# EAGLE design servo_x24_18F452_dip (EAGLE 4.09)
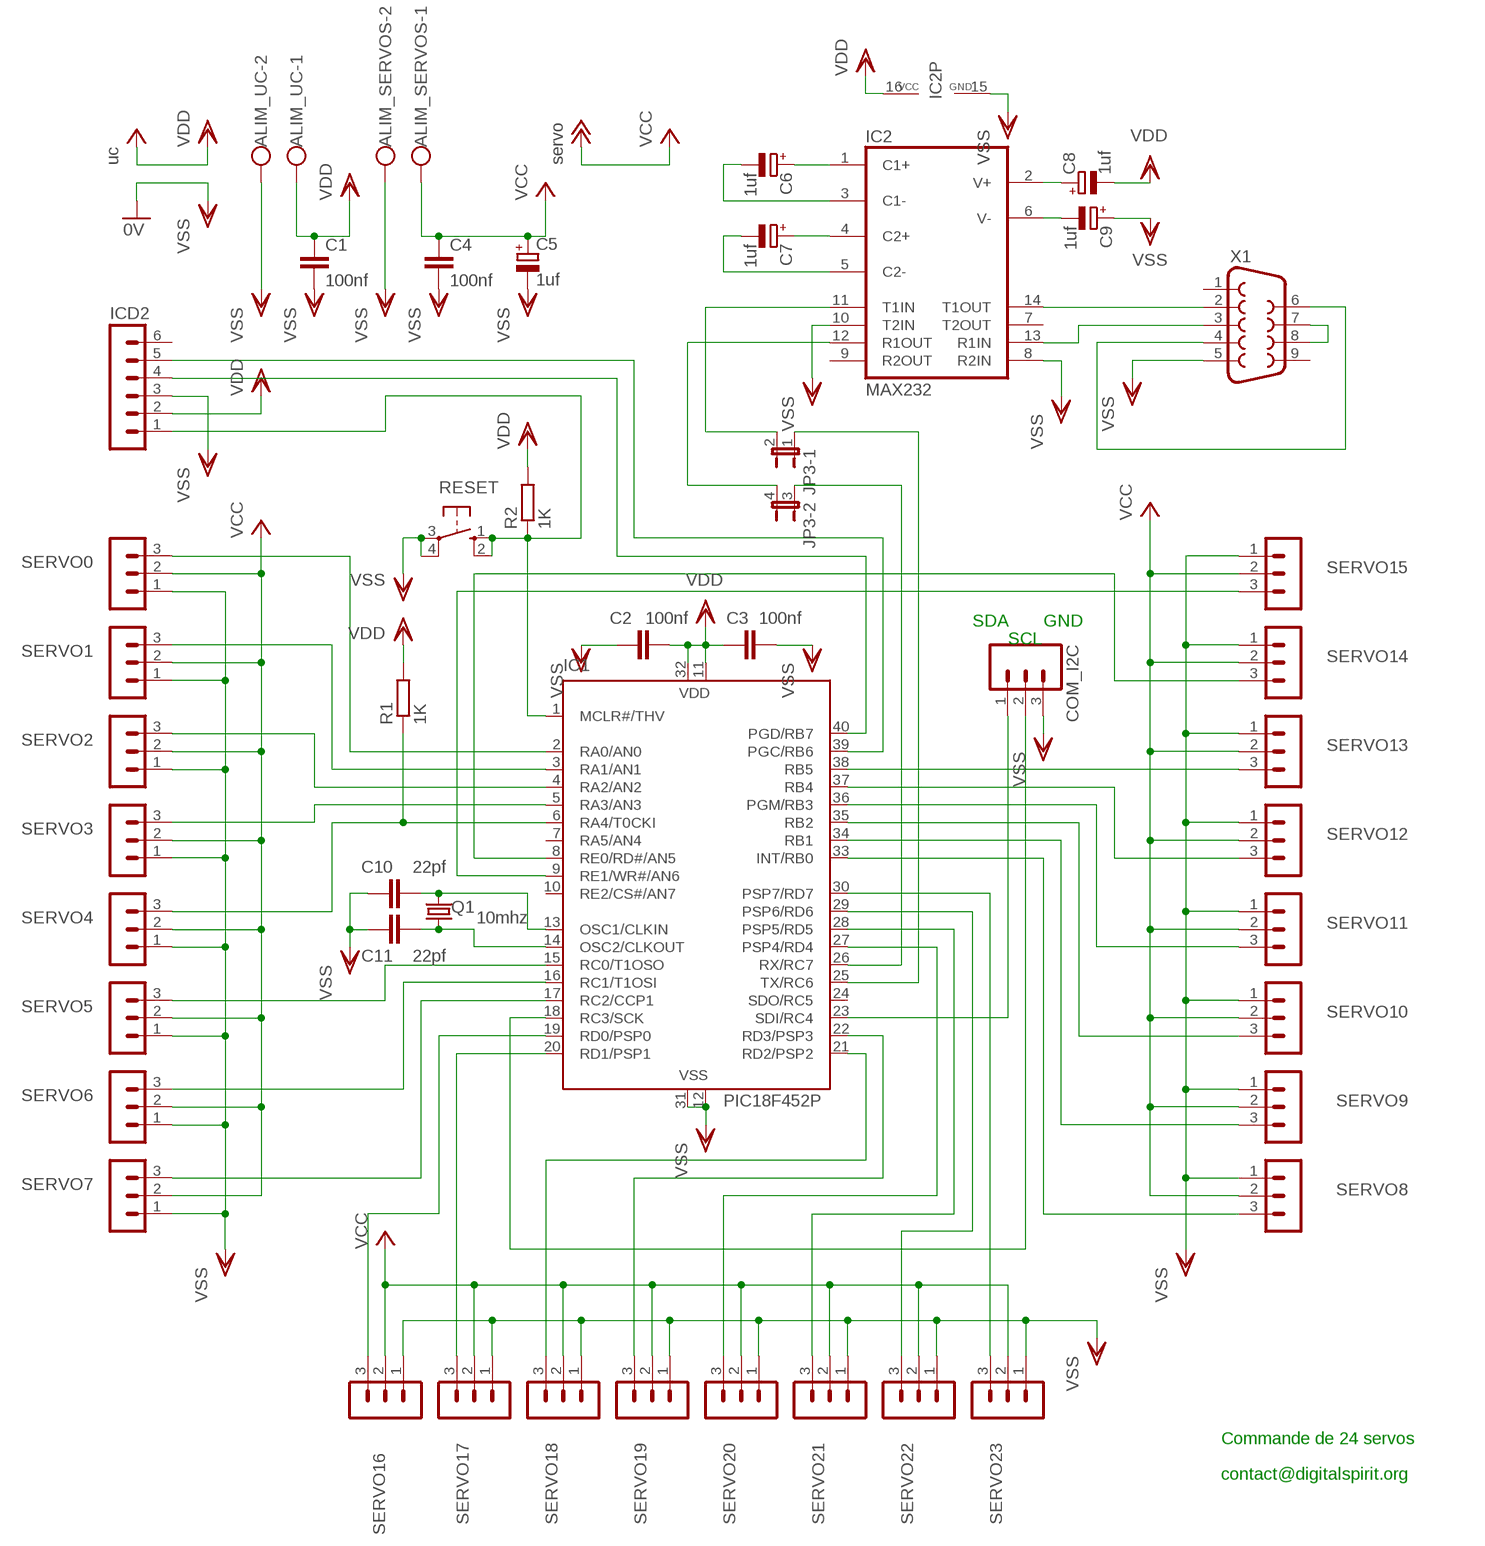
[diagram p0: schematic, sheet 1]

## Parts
ALIM_SERVOS  AK500/2  [AK500/2]
ALIM_UC  AK500/2  [AK500/2]
C1  100nf  C-EU050-025X075  [C050-025X075]
C2  100nf  C-EU050-025X075  [C050-025X075]
C3  100nf  C-EU050-025X075  [C050-025X075]
C4  100nf  C-EU050-025X075  [C050-025X075]
C5  1uf  CPOL-EUE2-4  [E2-4]
C6  1uf  CPOL-EUE2-4  [E2-4]
C7  1uf  CPOL-EUE2-4  [E2-4]
C8  1uf  CPOL-EUE2-4  [E2-4]
C9  1uf  CPOL-EUE2-4  [E2-4]
C10  22pf  C-EU050-024X044  [C050-024X044]
C11  22pf  C-EU050-024X044  [C050-024X044]
COM_I2C  M03  [03P]
IC1  PIC18F452P  PIC16F877P  [DIL40]
IC2  MAX232  [DIL16]
ICD2  MA06-1  [MA06-1]
JP3  JP2QE  [JP2Q]
Q1  10mhz  CRYTALHC49S  [HC49/S]
R1  1K  R-EU_0204/7  [0204/7]
R2  1K  R-EU_0204/7  [0204/7]
RESET  10-XX  [B3F-10XX]
SERVO0  MA03-1  [MA03-1]
SERVO1  MA03-1  [MA03-1]
SERVO2  MA03-1  [MA03-1]
SERVO3  MA03-1  [MA03-1]
SERVO4  MA03-1  [MA03-1]
SERVO5  MA03-1  [MA03-1]
SERVO6  MA03-1  [MA03-1]
SERVO7  MA03-1  [MA03-1]
SERVO8  MA03-1  [MA03-1]
SERVO9  MA03-1  [MA03-1]
SERVO10  MA03-1  [MA03-1]
SERVO11  MA03-1  [MA03-1]
SERVO12  MA03-1  [MA03-1]
SERVO13  MA03-1  [MA03-1]
SERVO14  MA03-1  [MA03-1]
SERVO15  MA03-1  [MA03-1]
SERVO16  MA03-1  [MA03-1]
SERVO17  MA03-1  [MA03-1]
SERVO18  MA03-1  [MA03-1]
SERVO19  MA03-1  [MA03-1]
SERVO20  MA03-1  [MA03-1]
SERVO21  MA03-1  [MA03-1]
SERVO22  MA03-1  [MA03-1]
SERVO23  MA03-1  [MA03-1]
X1  F09H  [F09H]

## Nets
N$1: IC1.2(RA0/AN0) SERVO0.3
N$2: IC1.3(RA1/AN1) SERVO1.3
N$3: IC1.4(RA2/AN2) SERVO2.3
N$4: IC1.5(RA3/AN3) SERVO3.3
N$5: IC1.6(RA4/T0CKI) R1.1 SERVO4.3
N$6: IC1.15(RC0/T1OSO) SERVO5.3
N$7: IC1.16(RC1/T1OSI) SERVO6.3
N$8: IC1.17(RC2/CCP1) SERVO7.3
N$9: COM_I2C.1 IC1.23(SDI/RC4)
N$10: IC1.33(INT/RB0) SERVO8.3
N$11: IC1.34(RB1) SERVO9.3
N$12: IC1.35(RB2) SERVO10.3
N$13: IC1.36(PGM/RB3) SERVO11.3
N$14: IC1.37(RB4) SERVO12.3
N$15: IC1.38(RB5) SERVO13.3
N$16: IC2.14(T1OUT) X1.2
N$17: IC1.25(TX/RC6) JP3.1
N$18: COM_I2C.2 IC1.18(RC3/SCK)
N$19: X1.4 X1.6
N$20: X1.7 X1.8
N$21: IC1.8(RE0/RD#/AN5) SERVO14.3
N$23: IC2.13(R1IN) X1.3
N$24: IC1.9(RE1/WR#/AN6) SERVO15.3
N$25: C11.2 IC1.14(OSC2/CLKOUT) Q1.1
N$26: IC2.12(R1OUT) JP3.4
N$27: C10.2 IC1.13(OSC1/CLKIN) Q1.2
N$28: IC2.11(T1IN) JP3.2
N$29: IC1.1(MCLR#/THV) ICD2.1 R2.1 RESET.1(S) RESET.2(S1)
N$30: C9.- IC2.6(V-)
N$31: IC1.26(RX/RC7) JP3.3
N$32: C6.- IC2.3(C1-)
N$33: IC1.19(RD0/PSP0) SERVO16.3
N$34: IC1.20(RD1/PSP1) SERVO17.3
N$35: IC1.21(RD2/PSP2) SERVO18.3
N$36: IC1.22(RD3/PSP3) SERVO19.3
N$37: IC1.27(PSP4/RD4) SERVO20.3
N$38: IC1.28(PSP5/RD5) SERVO21.3
N$39: IC1.29(PSP6/RD6) SERVO22.3
N$40: IC1.30(PSP7/RD7) SERVO23.3
N$41: C6.+ IC2.1(C1+)
N$42: C7.+ IC2.4(C2+)
N$43: C7.- IC2.5(C2-)
N$44: C8.+ IC2.2(V+)
RB6: IC1.39(PGC/RB6) ICD2.5
RB7: IC1.40(PGD/RB7) ICD2.4
VCC: ALIM_SERVOS.1 C4.1 C5.+ SERVO0.2 SERVO1.2 SERVO2.2 SERVO3.2 SERVO4.2 SERVO5.2 SERVO6.2 SERVO7.2 SERVO8.2 SERVO9.2 SERVO10.2 SERVO11.2 SERVO12.2 SERVO13.2 SERVO14.2 SERVO15.2 SERVO16.2 SERVO17.2 SERVO18.2 SERVO19.2 SERVO20.2 SERVO21.2 SERVO22.2 SERVO23.2 ; supply symbol labelled servo
VDD: ALIM_UC.1 C1.1 C2.1 C3.1 C8.- IC1.11(VDD) IC1.32(VDD) IC2.16(VCC) ICD2.2 R1.2 R2.2 ; supply symbol labelled uc
VSS: ALIM_SERVOS.2 ALIM_UC.2 C1.2 C2.2 C3.2 C4.2 C5.- C9.+ C10.1 C11.1 COM_I2C.3 IC1.12(VSS) IC1.31(VSS) IC2.8(R2IN) IC2.10(T2IN) IC2.15(GND) ICD2.3 RESET.3(P) RESET.4(P1) SERVO0.1 SERVO1.1 SERVO2.1 SERVO3.1 SERVO4.1 SERVO5.1 SERVO6.1 SERVO7.1 SERVO8.1 SERVO9.1 SERVO10.1 SERVO11.1 SERVO12.1 SERVO13.1 SERVO14.1 SERVO15.1 SERVO16.1 SERVO17.1 SERVO18.1 SERVO19.1 SERVO20.1 SERVO21.1 SERVO22.1 SERVO23.1 X1.5 ; supply symbol labelled 0V
Unconnected: IC1.7(RA5/AN4) IC1.10(RE2/CS#/AN7) IC1.24(SDO/RC5) IC2.7(T2OUT) IC2.9(R2OUT) ICD2.6 X1.1 X1.9

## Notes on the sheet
- SDA | GND
- SCL
- Commande de 24 servos
- contact@digitalspirit.org

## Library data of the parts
ALIM_SERVOS ALIM_UC = con-ptr500:AK500/2: CONNECTOR
C1-C4 C10 C11 = rcl:C-EU: CAPACITOR, European symbol
C5-C9 = rcl:CPOL-EU: POLARIZED CAPACITOR, European symbol
COM_I2C = con-amp-quick:M03: AMP QUICK CONNECTOR
IC1 = microchip:PIC16F87*: MICROCONTROLLER
IC2 = maxim:MAX232: RS232 TRANSEIVER
ICD2 = con-lstb:MA06-1: PIN HEADER
JP3 = jumper:JP2QE: JUMPER
Q1 = crystal:CRYTAL: CRYSTAL
R1 R2 = rcl:R-EU_: RESISTOR, European symbol
RESET = switch-omron:10-XX: OMRON SWITCH
SERVO0 SERVO1-SERVO23 = con-lstb:MA03-1: PIN HEADER
X1 = con-subd:F09: SUB-D

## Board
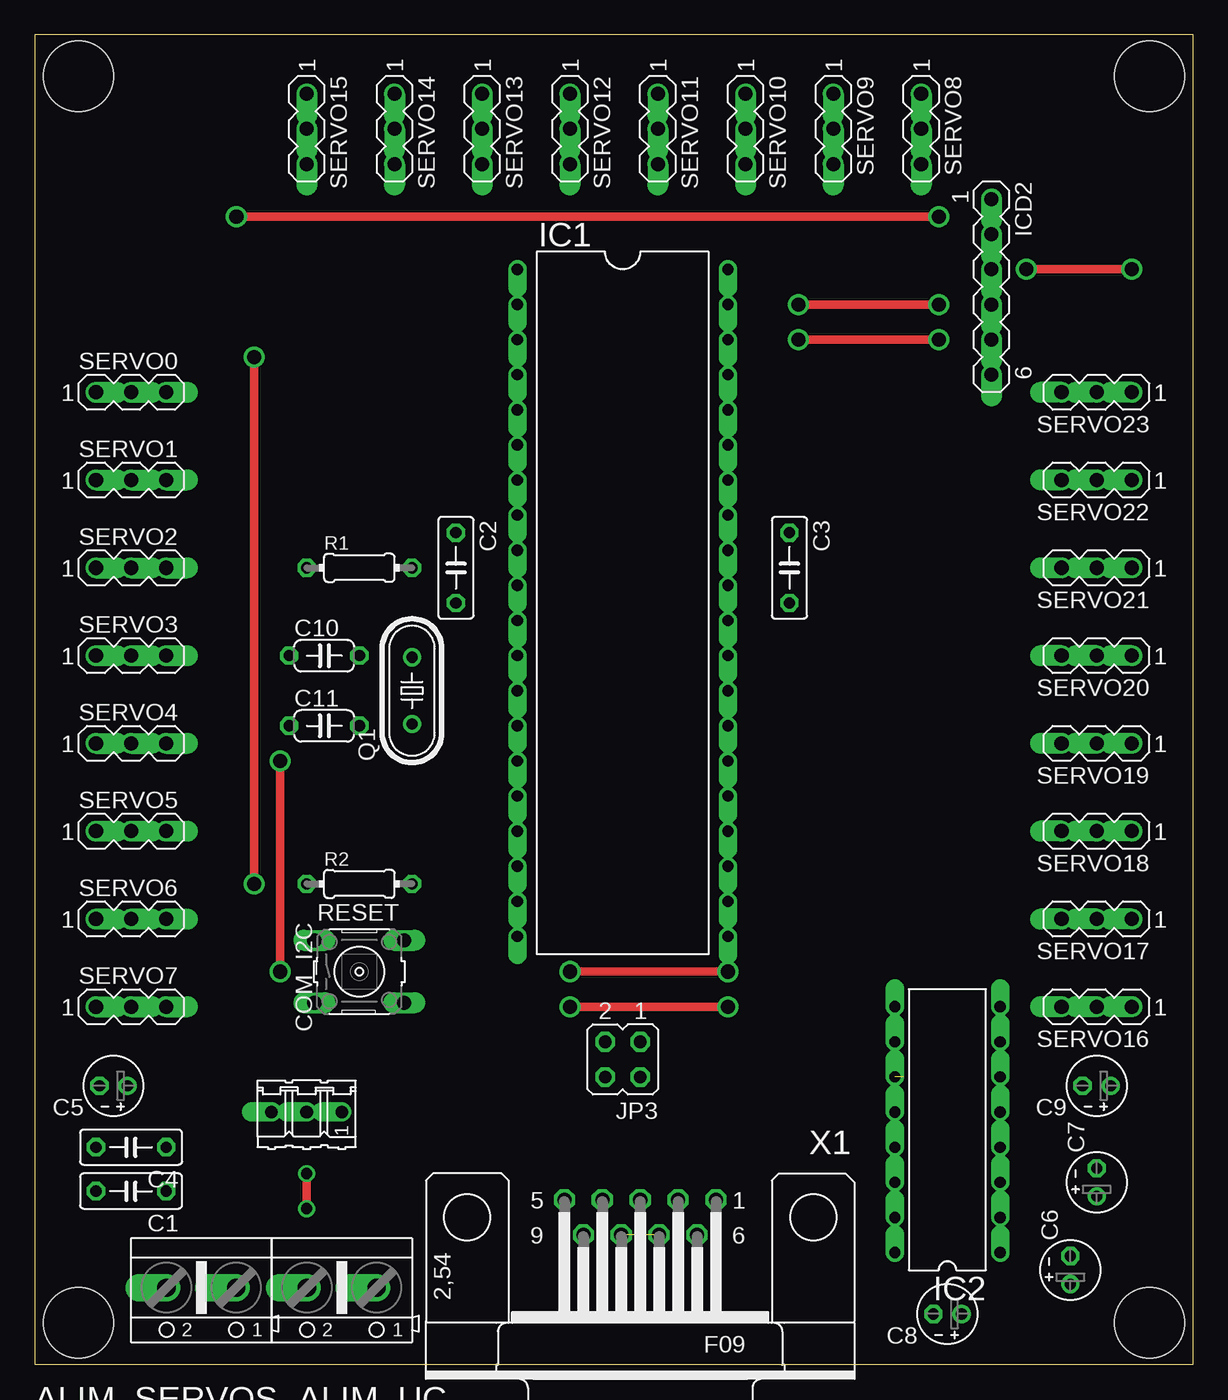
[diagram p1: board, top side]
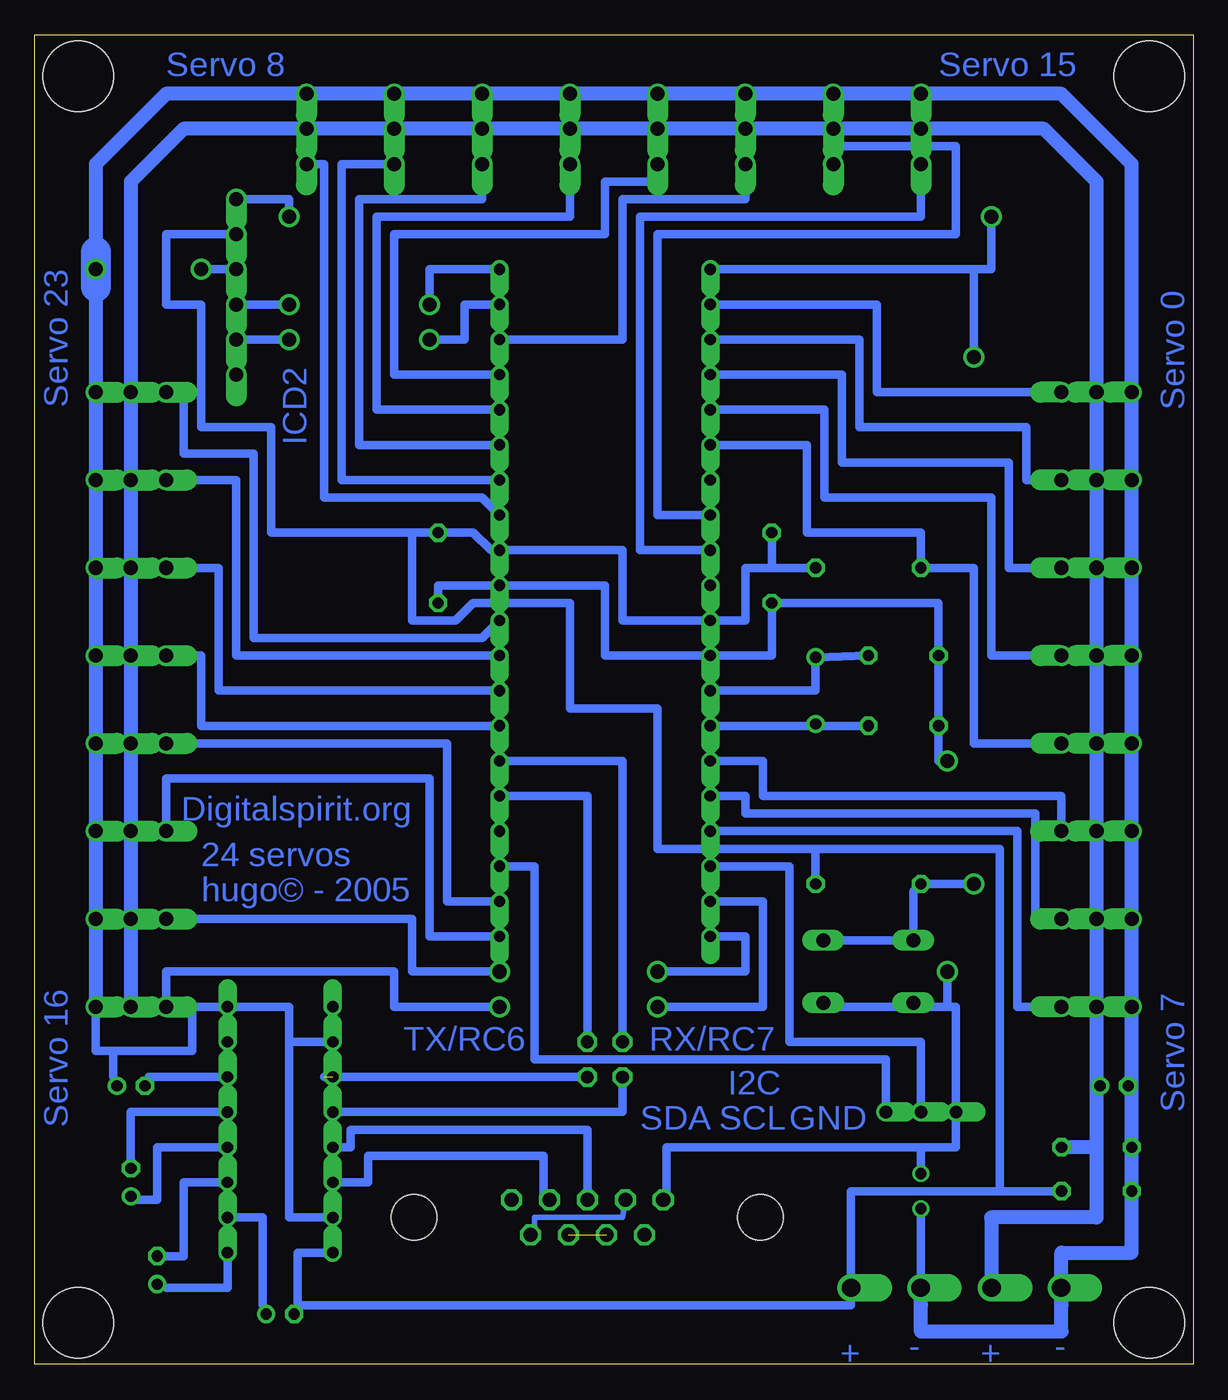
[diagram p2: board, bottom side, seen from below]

Size 83.8 x 96.19 mm. Coordinates in mm from the lower left corner, seen from the top.
Outline: 0,0 83.8,0 83.8,96.19 0,96.19 0,0
Copper layers used: Top, Bottom
Holes 5.08 mm at 3.17,3.01 3.17,93.18 80.64,93.18 80.64,3.01

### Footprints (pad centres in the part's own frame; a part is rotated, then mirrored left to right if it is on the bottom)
AK500/2 = drill 1.321 offset: 1 -2.515,0; 2 2.515,0
C050-025X075 = drill 0.813 octagon: 1 -2.54,0; 2 2.54,0
E2-4 = drill 0.813 pad 1.27 round: + -1.016,0 | drill 0.813 pad 1.27 octagon: - 1.016,0
C050-024X044 = drill 0.813 octagon: 1 -2.54,0; 2 2.54,0
03P = drill 0.914 offset: 1 -2.54,0; 2 0,0; 3 2.54,0
DIL40 = drill 0.813 offset: 1 -24.13,-7.62; 2 -21.59,-7.62; 3 -19.05,-7.62; 4 -16.51,-7.62; 5 -13.97,-7.62; 6 -11.43,-7.62; 7 -8.89,-7.62; 8 -6.35,-7.62; 9 -3.81,-7.62; 10 -1.27,-7.62; 11 1.27,-7.62; 12 3.81,-7.62; 13 6.35,-7.62; 14 8.89,-7.62; 15 11.43,-7.62; 16 13.97,-7.62; 17 16.51,-7.62; 18 19.05,-7.62; 19 21.59,-7.62; 20 24.13,-7.62; 21 24.13,7.62; 22 21.59,7.62; 23 19.05,7.62; 24 16.51,7.62; 25 13.97,7.62; 26 11.43,7.62; 27 8.89,7.62; 28 6.35,7.62; 29 3.81,7.62; 30 1.27,7.62; 31 -1.27,7.62; 32 -3.81,7.62; 33 -6.35,7.62; 34 -8.89,7.62; 35 -11.43,7.62; 36 -13.97,7.62; 37 -16.51,7.62; 38 -19.05,7.62; 39 -21.59,7.62; 40 -24.13,7.62
DIL16 = drill 0.813 offset: 1 -8.89,-3.81; 2 -6.35,-3.81; 3 -3.81,-3.81; 4 -1.27,-3.81; 5 1.27,-3.81; 6 3.81,-3.81; 7 6.35,-3.81; 8 8.89,-3.81; 9 8.89,3.81; 10 6.35,3.81; 11 3.81,3.81; 12 1.27,3.81; 13 -1.27,3.81; 14 -3.81,3.81; 15 -6.35,3.81; 16 -8.89,3.81
MA06-1 = drill 1.016 offset: 1 -6.35,0; 2 -3.81,0; 3 -1.27,0; 4 1.27,0; 5 3.81,0; 6 6.35,0
JP2Q = drill 0.914 octagon: 1 -1.27,-1.27; 2 -1.27,1.27; 3 1.27,-1.27; 4 1.27,1.27
HC49/S = drill 0.813 round: 1 -2.413,0; 2 2.413,0
0204/7 = drill 0.813 octagon: 1 -3.81,0; 2 3.81,0
B3F-10XX = drill 1.016 long: 1 -3.251,2.261; 2 3.251,2.261; 3 -3.251,-2.261; 4 3.251,-2.261
MA03-1 = drill 1.016 offset: 1 -2.54,0; 2 0,0; 3 2.54,0
F09H = drill 1.016 octagon: 1 -5.486,-1.27; 2 -2.743,-1.27; 3 0,-1.27; 4 2.743,-1.27; 5 5.486,-1.27; 6 -4.115,1.27; 7 -1.372,1.27; 8 1.372,1.27; 9 4.115,1.27 | hole 3.302: -12.522,0; 12.522,0

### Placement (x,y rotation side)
ALIM_SERVOS  12.06,5.55 180 top
ALIM_UC  22.22,5.55 180 top
C1  6.98,12.54 180 top
C2  30.47,57.62 270 top
C3  54.61,57.62 270 top
C4  6.98,15.71 180 top
C5  5.71,20.15 180 top
C6  74.92,6.82 90 top
C7  76.83,13.17 90 top
C8  66.03,3.64 180 top
C9  76.83,20.15 180 top
C10  20.95,51.27 0 top
C11  20.95,46.19 0 top
COM_I2C  19.68,18.25 180 top
IC1  42.54,55.08 270 top
IC2  66.03,16.98 90 top
ICD2  69.21,77.94 270 top
JP3  42.54,22.06 180 top
Q1  27.3,48.73 90 top
R1  23.49,57.62 0 top
R2  23.49,34.76 0 top
RESET  23.49,28.41 0 top
SERVO0  6.98,70.32 0 top
SERVO1  6.98,63.97 0 top
SERVO2  6.98,57.62 0 top
SERVO3  6.98,51.27 0 top
SERVO4  6.98,44.92 0 top
SERVO5  6.98,38.57 0 top
SERVO6  6.98,32.22 0 top
SERVO7  6.98,25.87 0 top
SERVO8  64.13,89.37 270 top
SERVO9  57.78,89.37 270 top
SERVO10  51.43,89.37 270 top
SERVO11  45.08,89.37 270 top
SERVO12  38.73,89.37 270 top
SERVO13  32.38,89.37 270 top
SERVO14  26.03,89.37 270 top
SERVO15  19.68,89.37 270 top
SERVO16  76.83,25.87 180 top
SERVO17  76.83,32.22 180 top
SERVO18  76.83,38.57 180 top
SERVO19  76.83,44.92 180 top
SERVO20  76.83,51.27 180 top
SERVO21  76.83,57.62 180 top
SERVO22  76.83,63.97 180 top
SERVO23  76.83,70.32 180 top
X1  43.81,10.63 180 top

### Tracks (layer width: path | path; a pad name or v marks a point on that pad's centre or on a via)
N$1
  Bottom 0.61: SERVO0.3 22.86,70.32 22.86,76.67 IC1.2
N$2
  Bottom 0.61: SERVO1.3 12.06,63.97 12.06,67.78 24.12,67.78 24.12,74.13 IC1.3
N$3
  Bottom 0.61: SERVO2.3 13.33,57.62 13.33,65.24 25.39,65.24 25.39,71.59 IC1.4
N$4
  Bottom 0.61: SERVO3.3 14.6,51.27 14.6,62.7 26.66,62.7 26.66,69.05 IC1.5
N$5
  Bottom 0.61: SERVO4.3 15.87,44.92 15.87,57.62 R1.1 19.68,60.16 27.93,60.16 27.93,66.51 IC1.6
N$6
  Bottom 0.61: IC1.15 31.11,43.65 31.11,41.11 9.52,41.11 SERVO5.3
N$7
  Bottom 0.61: SERVO6.3 11.43,32.22 11.43,39.84 32.38,39.84 32.38,41.11 IC1.16
N$8
  Bottom 0.61: SERVO7.3 12.7,25.87 12.7,38.57 IC1.17
N$9
  Bottom 0.61: IC1.23 47.62,36.03 47.62,22.06 22.22,22.06 COM_I2C.1
N$10
  Bottom 0.61: SERVO8.3 62.86,86.83 62.86,62.7 51.43,62.7 IC1.33
N$11
  Bottom 0.61: IC1.34 61.59,63.97 61.59,86.83 SERVO9.3
N$12
  Bottom 0.61: IC1.35 60.32,66.51 60.32,84.29 51.43,84.29 SERVO10.3
N$13
  Bottom 0.61: IC1.36 59.05,69.05 59.05,83.02 45.08,83.02 SERVO11.3
N$14
  Bottom 0.61: IC1.37 57.78,71.59 57.78,81.75 42.54,81.75 42.54,85.56 38.73,85.56 SERVO12.3
N$15
  Bottom 0.61: IC1.38 41.27,74.13 41.27,84.29 32.38,84.29 SERVO13.3
N$16
  Bottom 0.61: X1.2 46.98,11.9 46.98,15.08 59.69,15.08 59.69,13.17 IC2.14
N$17
  Bottom 0.61: JP3.1 43.81,41.11 IC1.25
N$18
  Bottom 0.61: IC1.18 29.2,36.03 29.2,23.33 19.68,23.33 COM_I2C.2
N$19
  Bottom 0.406: X1.4 41.27,10.63 47.62,10.63 47.62,9.36 X1.6
N$20  (1 unrouted)
N$21
  Bottom 0.61: IC1.8 38.73,61.43 38.73,81.75 17.14,81.75 17.14,88.1 26.03,88.1 SERVO14.3
N$23
  Bottom 0.61: IC2.13 60.96,15.71 60.96,16.98 43.81,16.98 X1.3
N$24
  Bottom 0.61: IC1.9 40,58.89 40,83.02 19.68,83.02 SERVO15.3
N$25
  Bottom 0.61: 27.3,46.19 IC1.14 | 27.3,46.19 Q1.1 | C11.2 27.3,46.19
N$26
  Bottom 0.61: IC2.12 41.27,18.25 JP3.4
N$27
  Bottom 0.61: IC1.13 27.3,48.73 Q1.2 C10.2
N$28  (1 unrouted)
  Bottom 0.61: JP3.2 62.86,20.79
N$29  (via drill 1.02)
  Top 0.61: v15.87,34.76 v15.87,72.86 | v14.6,83.02 v65.4,83.02
  Bottom 0.61: RESET.1 RESET.2 | RESET.1 19.96,30.67 19.68,30.95 | RESET.1 20.24,34.2 R2.1 v15.87,34.76 | v15.87,72.86 15.87,79.21 | 15.87,79.21 IC1.1 | ICD2.1 65.4,84.29 v65.4,83.02 | v14.6,83.02 14.6,79.21 15.87,79.21
N$30
  Bottom 0.61: IC2.6 75.56,20.79 75.56,20.15 C9.-
N$31
  Bottom 0.61: IC1.26 41.27,43.65 JP3.3
N$32
  Bottom 0.61: 70.48,13.17 IC2.3 73.02,13.17 73.02,7.84 C6.-
N$33  (via drill 1.02)
  Top 0.61: v38.73,25.87 v50.16,25.87
  Bottom 0.61: IC1.19 31.11,33.49 31.11,25.87 v38.73,25.87 | v50.16,25.87 57.78,25.87 57.78,28.41 74.29,28.41 SERVO16.3
N$34  (via drill 1.02)
  Top 0.61: v38.73,28.41 v50.16,28.41
  Bottom 0.61: SERVO17.3 56.51,32.22 56.51,28.41 v50.16,28.41 | v38.73,28.41 32.38,28.41 32.38,30.95 IC1.20
N$35
  Bottom 0.61: IC1.21 55.24,30.95 55.24,42.38 74.29,42.38 SERVO18.3
N$36
  Bottom 0.61: IC1.22 53.97,33.49 53.97,44.92 SERVO19.3
N$37
  Bottom 0.61: SERVO20.3 71.75,51.27 71.75,46.19 IC1.27
N$38
  Bottom 0.61: IC1.28 70.48,48.73 70.48,57.62 SERVO21.3
N$39
  Bottom 0.61: IC1.29 69.21,51.27 69.21,63.97 SERVO22.3
N$40
  Bottom 0.61: SERVO23.3 73.02,70.32 73.02,65.88 67.94,65.88 67.94,52.54 51.43,52.54 IC1.30
N$41
  Bottom 0.61: IC2.1 69.84,5.55 74.29,5.55 C6.+
N$42
  Bottom 0.61: IC2.4 74.92,15.71 74.92,11.9 76.83,11.9 C7.+
N$43
  Bottom 0.61: IC2.5 76.83,18.25 C7.- 76.83,13.81
N$44
  Bottom 0.61: IC2.2 67.3,10.63 67.3,4.28 C8.+
RB6  (via drill 1.02)
  Top 0.61: v55.24,74.13 v65.4,74.13
  Bottom 0.61: v55.24,74.13 52.7,74.13 52.7,76.67 IC1.39 | v65.4,74.13 ICD2.5
RB7  (via drill 1.02)
  Top 0.61: v55.24,76.67 v65.4,76.67
  Bottom 0.61: IC1.40 55.24,79.21 v55.24,76.67 | v65.4,76.67 ICD2.4
VCC
  Bottom 1.016: SERVO19.2 SERVO20.2 SERVO21.2 SERVO22.2 SERVO23.2 76.83,85.56 73.02,89.37 SERVO8.2 SERVO9.2 SERVO10.2 SERVO11.2 SERVO12.2 SERVO13.2 SERVO14.2 SERVO15.2 10.79,89.37 6.98,85.56 SERVO0.2 SERVO1.2 SERVO2.2 SERVO3.2 SERVO4.2 SERVO5.2 SERVO6.2 SERVO7.2 6.98,20.15 | SERVO19.2 76.83,43.65 | SERVO19.2 SERVO18.2 SERVO17.2 SERVO16.2 | ALIM_SERVOS.1 14.58,9.34 14.6,10.63 6.98,10.63 6.98,15.71 | 6.98,15.71 6.98,20.15 | 6.98,20.15 C5.+ | 6.98,15.71 C4.1
VDD
  Bottom 0.61: IC2.16 64.77,8.09 64.77,4.28 | 64.77,4.28 C8.- | 13.97,12.54 24.76,12.54 ALIM_UC.1 24.76,5.55 24.76,4.28 64.77,4.28 | 27.3,37.3 38.73,37.3 38.73,47.46 45.08,47.46 45.08,55.08 52.07,55.08 53.34,53.81 56.51,53.81 56.51,60.16 | 27.3,37.3 R2.2 | 27.3,37.3 13.97,37.3 13.97,12.54 | 30.47,57.62 32.38,57.62 32.38,53.81 IC1.11 41.27,53.81 41.27,58.89 IC1.32 50.8,58.89 52.07,60.16 C3.1 56.51,60.16 | 30.47,57.62 R1.2 | ICD2.2 74.29,81.75 74.29,76.67 71.75,76.67 71.75,67.78 66.67,67.78 66.67,60.16 56.51,60.16 | 30.47,57.62 C2.1 | C1.1 13.97,12.54
VSS  (via drill 0.81, 1.02)
  Top 0.61: v79.37,79.21 v71.75,79.21 | v19.68,11.27 v19.68,13.81 | v17.77,28.41 v17.77,43.65
  Bottom 0.61: IC2.15 65.4,10.63 65.4,23.33 | 65.4,23.33 IC2.10 | 65.4,23.33 65.4,25.87 IC2.8 72.38,25.87 72.38,22.7 78.1,22.7 | v71.75,79.21 ICD2.3 | X1.5 38.1,11.9 38.1,15.71 19.68,15.71 | 19.68,15.71 17.14,15.71 COM_I2C.3 17.14,25.87 17.77,25.87 | 17.77,25.87 19.68,25.87 | 19.68,25.87 27.3,25.87 27.3,26.15 RESET.4 | RESET.3 19.68,26.15 19.68,25.87 | SERVO16.1 79.37,22.7 78.1,22.7 | 19.68,4.28 v19.68,11.27 | v19.68,13.81 19.68,15.71 | v17.77,43.65 18.41,43.65 C11.1 C10.1 18.41,55.08 C2.2 30.47,51.27 IC1.12 42.54,51.27 42.54,56.35 IC1.31 54.61,56.35 C3.2 | 17.77,25.87 v17.77,28.41 | C9.+ 78.1,20.79 78.1,22.7
  Bottom 1.016: SERVO0.1 SERVO1.1 SERVO2.1 SERVO3.1 SERVO4.1 | SERVO4.1 SERVO5.1 SERVO6.1 SERVO7.1 4.44,20.15 | SERVO4.1 4.44,86.83 9.52,91.91 SERVO15.1 SERVO14.1 SERVO13.1 SERVO12.1 SERVO11.1 SERVO10.1 SERVO9.1 SERVO8.1 74.29,91.91 79.37,86.83 79.37,80.48 v79.37,79.21 79.37,77.94 SERVO23.1 SERVO22.1 SERVO21.1 SERVO20.1 SERVO19.1 SERVO18.1 SERVO17.1 SERVO16.1 | 9.52,4.28 9.54,4.3 9.54,6.79 9.52,8.09 4.44,8.09 C1.2 C4.2 4.44,20.15 | 9.52,4.28 ALIM_SERVOS.2 | 9.52,4.28 9.52,2.38 19.68,2.38 19.68,4.28 ALIM_UC.2 | 4.44,20.15 C5.-
  Bottom 2.184: 79.37,80.48 79.37,77.94

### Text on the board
Bottom: Servo 15 | Servo 8 | Servo 23 | Servo 0 | ICD2 | Digitalspirit.org | 24 servos | hugo© - 2005 | Servo 16 | RX/RC7 | TX/RC6 | I2C | Servo 7 | GND | SCL | SDA | - | - | + | +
